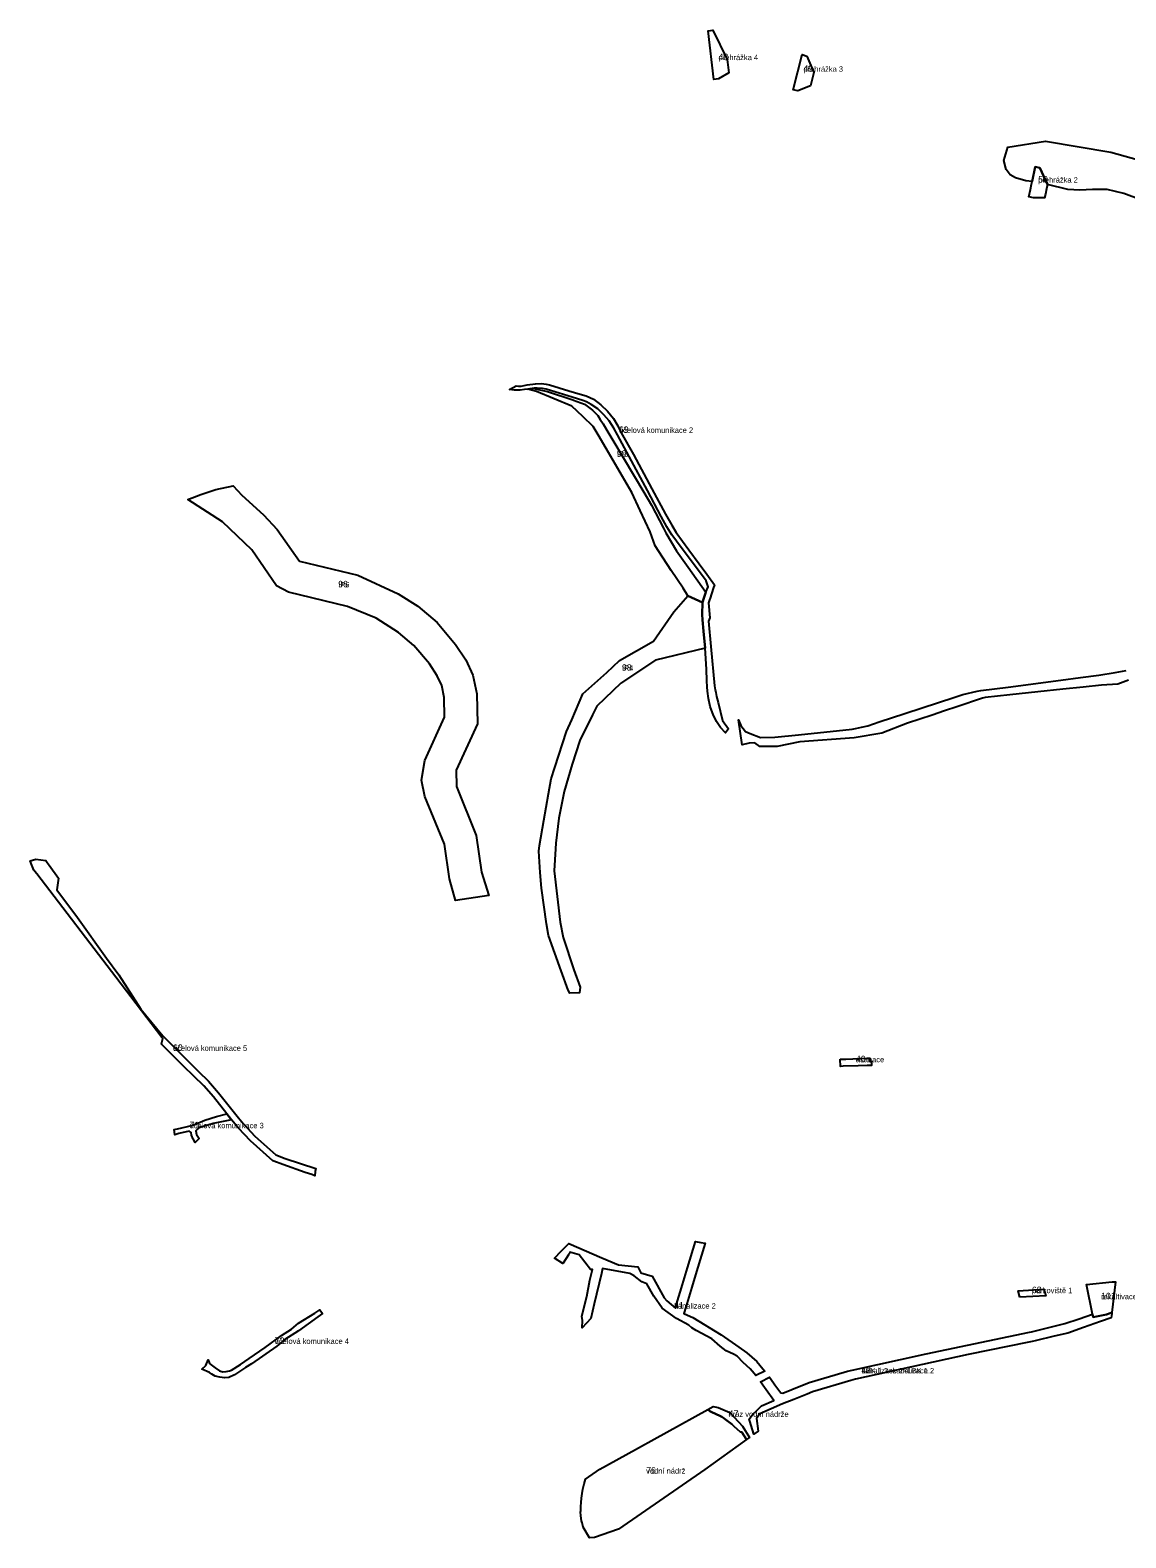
# Model space of a CAD drawing. Extents: x -535270 to -532834, y -1165802 to -1163869.
# Drawn here: x -535270 to -534261, y -1165554 to -1164165 of the extents above; entities that cross this region are included whole.
import ezdxf

# ---------------------------------------------------------------- set-up
doc = ezdxf.new("R2010")
doc.units = 0
for name, color, linetype in [('96070023', 7, 'Continuous'), ('96120023', 7, 'Continuous'), ('96140023', 7, 'Continuous'), ('ID_A', 7, 'Continuous'), ('ID_VPO', 7, 'Continuous'), ('ID_VPS', 7, 'Continuous')]:
    doc.layers.add(name, color=color, linetype=linetype)

msp = doc.modelspace()

# ---------------------------------------------------------------- linework, layer by layer
at = {"layer": '96070023'}
for points in [[(-534524.4, -1165113.2), (-534522, -1165113.1), (-534519, -1165113), (-534499.6, -1165112.1), (-534497, -1165112), (-534496.9, -1165115.3), (-534495.4, -1165115.2), (-534495.3, -1165118.9), (-534499.4, -1165119), (-534507.6, -1165119.3), (-534521.5, -1165119.6), (-534524, -1165119.7)], [(-534273.9, -1165318.2), (-534270.6, -1165318.2), (-534274, -1165346.4), (-534275.6, -1165346.9), (-534279.1, -1165348.2), (-534291.4, -1165350.8), (-534292, -1165347.8), (-534297.5, -1165320.7)]]:
    msp.add_lwpolyline(points, close=True, dxfattribs=at)
at = {"layer": '96120023'}
for points in [[(-534628.3, -1164192.3), (-534626.9, -1164204.7), (-534636.3, -1164210.1), (-534640.7, -1164210.6), (-534645.8, -1164165.9), (-534641.5, -1164165.3)], [(-534555.1, -1164189.1), (-534548.6, -1164204.4), (-534551.7, -1164216.5), (-534563.2, -1164221.3), (-534567.5, -1164220.3), (-534559.2, -1164187.6)], [(-534349.1, -1164312.1), (-534348, -1164307), (-534347.5, -1164304.6), (-534344.6, -1164291.1), (-534340.3, -1164292), (-534333.4, -1164307.5), (-534334.2, -1164311.5), (-534335.3, -1164316.4), (-534336, -1164319.7), (-534346.2, -1164319.7), (-534350.5, -1164318.8)], [(-534644.6, -1164690), (-534645.4, -1164692.8), (-534644.3, -1164706.7), (-534645.6, -1164709.7), (-534643.5, -1164733.1), (-534640.1, -1164769.3), (-534639.4, -1164772.9), (-534639.2, -1164773.8), (-534638.9, -1164775.4), (-534638.1, -1164779.1), (-534636.5, -1164784.7), (-534632.7, -1164801.2), (-534627.2, -1164808.9), (-534629.9, -1164812.5), (-534634.4, -1164807.5), (-534638.1, -1164802), (-534641.2, -1164795.7), (-534642.9, -1164791.6), (-534644, -1164788.3), (-534645.4, -1164781), (-534646.5, -1164774.2), (-534646.9, -1164770.1), (-534647, -1164764.5), (-534647.3, -1164753.7), (-534648.6, -1164734.4), (-534650.2, -1164718.7), (-534651.1, -1164708.5), (-534651.3, -1164703.4), (-534651, -1164692.3), (-534649.9, -1164688.6), (-534647.9, -1164682.8), (-534645.8, -1164678), (-534647.6, -1164672.4), (-534658.3, -1164658.1), (-534670.7, -1164641.7), (-534679.2, -1164630.1), (-534683.8, -1164622.8), (-534689, -1164613.3), (-534701.7, -1164589.4), (-534718.5, -1164558), (-534729.3, -1164538), (-534732.8, -1164531.8), (-534737.1, -1164525.2), (-534741.8, -1164519.5), (-534747.5, -1164514.1), (-534753.5, -1164510.1), (-534758, -1164507.7), (-534761.2, -1164506.4), (-534771.2, -1164503.3), (-534795, -1164495.9), (-534798.4, -1164495.2), (-534803.3, -1164494.9), (-534806.1, -1164495), (-534811.9, -1164495.8), (-534815.1, -1164496.4), (-534819, -1164496.8), (-534821.8, -1164496.9), (-534824.6, -1164496.8), (-534828.8, -1164496.4), (-534822.7, -1164493), (-534820.5, -1164493.1), (-534817.9, -1164493.1), (-534812.4, -1164492), (-534804.7, -1164491), (-534799.2, -1164490.8), (-534797.2, -1164490.9), (-534795, -1164491.2), (-534791.9, -1164491.9), (-534774, -1164497.4), (-534763.8, -1164500.7), (-534758.1, -1164502.1), (-534751.3, -1164505.2), (-534744.6, -1164510.4), (-534738.5, -1164516.3), (-534733.1, -1164523.1), (-534729.1, -1164529.8), (-534725.8, -1164536.1), (-534714.7, -1164556.1), (-534697.6, -1164587.6), (-534685, -1164611.1), (-534679.4, -1164621.2), (-534675.4, -1164627.9), (-534663.7, -1164644), (-534654.2, -1164656.8), (-534647.1, -1164666.5), (-534639.9, -1164676.1), (-534641.3, -1164679.6), (-534644, -1164688.3)], [(-535148.1, -1165091.7), (-535115.2, -1165124.5), (-535105.9, -1165133.4), (-535096.8, -1165144), (-535078.4, -1165167), (-535073.7, -1165172.7), (-535063.2, -1165184.1), (-535055.1, -1165191.2), (-535043.9, -1165201.1), (-535035.4, -1165204.6), (-535007.2, -1165213.8), (-535007.6, -1165216.5), (-535008.2, -1165220.6), (-535010.9, -1165219.4), (-535017.1, -1165217.3), (-535037.6, -1165210.2), (-535045.9, -1165206.9), (-535046.6, -1165206.7), (-535067.4, -1165188.4), (-535078.2, -1165176.7), (-535084.7, -1165168.8), (-535089, -1165163.4), (-535101.4, -1165147.9), (-535110.2, -1165137.6), (-535119.4, -1165128.8), (-535128.9, -1165119.5), (-535141.3, -1165107.1), (-535144, -1165104.4), (-535149.3, -1165099.3), (-535149, -1165097.8), (-535148, -1165094), (-535149, -1165093), (-535191.4, -1165037.5), (-535264.1, -1164942.3), (-535264.3, -1164942.1), (-535266.7, -1164938.9), (-535268.8, -1164934.5), (-535270.2, -1164930.3), (-535264.9, -1164928.9), (-535255.8, -1164930.2), (-535254.7, -1164931.8), (-535252.7, -1164934.5), (-535244.1, -1164946.4), (-535245.6, -1164957.1), (-535226.5, -1164982.7), (-535199.9, -1165019.9), (-535188.7, -1165035.4), (-535168.4, -1165067)], [(-535113.6, -1165171), (-535109.5, -1165169.3), (-535098.7, -1165165.8), (-535089, -1165163.4), (-535084.7, -1165168.8), (-535101.6, -1165172.4), (-535114.6, -1165176.2), (-535117.5, -1165179.1), (-535117.1, -1165182.5), (-535114.7, -1165186.1), (-535118.3, -1165189.9), (-535119.5, -1165187.7), (-535120, -1165186.8), (-535121.5, -1165183.2), (-535122, -1165180.7), (-535123.8, -1165179.5), (-535133.4, -1165181.6), (-535136.9, -1165182.6), (-535137.7, -1165177.7), (-535136, -1165177.4), (-535131.9, -1165176.7), (-535124.1, -1165174.8), (-535120.4, -1165173.7), (-535119.2, -1165173.2), (-535118.7, -1165173.1)], [(-534619, -1165386.7), (-534622.6, -1165384.9), (-534629.2, -1165381.7), (-534634.9, -1165377.4), (-534642.5, -1165370.8), (-534656.8, -1165362.9), (-534660.9, -1165360.4), (-534663.7, -1165358), (-534675, -1165352), (-534688.2, -1165342.4), (-534695.9, -1165331.3), (-534702.2, -1165320.1), (-534706.9, -1165318.1), (-534714, -1165312.5), (-534718.1, -1165310.4), (-534743.1, -1165306), (-534744.1, -1165310.6), (-534750.7, -1165338.5), (-534753.9, -1165352), (-534761.8, -1165360.4), (-534761.6, -1165353.7), (-534762.3, -1165349.7), (-534757.7, -1165331.8), (-534754.7, -1165316.6), (-534752.5, -1165306.9), (-534754.2, -1165306.7), (-534764.5, -1165293.4), (-534773.2, -1165290.9), (-534773.5, -1165292.1), (-534774.3, -1165293.3), (-534779.5, -1165300.9), (-534779.8, -1165301.4), (-534787.4, -1165296.3), (-534781.2, -1165289.9), (-534780.2, -1165288.9), (-534774.2, -1165282.7), (-534743.6, -1165295.9), (-534728.3, -1165302.6), (-534710.5, -1165304.2), (-534707.8, -1165310), (-534697.3, -1165312.9), (-534686.2, -1165332.9), (-534683.8, -1165335.5), (-534676, -1165342.3), (-534674.9, -1165338.6), (-534669.5, -1165320.6), (-534664.9, -1165305.3), (-534657.6, -1165281.1), (-534652.5, -1165281.9), (-534648.7, -1165282.5), (-534656.5, -1165308.5), (-534660.8, -1165323.1), (-534666.4, -1165341.5), (-534668.1, -1165347.2), (-534662.1, -1165350.1), (-534659.9, -1165351.1), (-534634, -1165367.1), (-534617.7, -1165378.2), (-534610.2, -1165383.4), (-534601, -1165391.4), (-534598.2, -1165394.8), (-534597, -1165396.3), (-534593.7, -1165400.3), (-534601.4, -1165404.2), (-534602, -1165404.5), (-534605.2, -1165400.5), (-534607, -1165398.3), (-534613.5, -1165392.3)], [(-534358.8, -1165332.2), (-534360.4, -1165326.3), (-534336.7, -1165324.9), (-534335, -1165330.9)], [(-535053.9, -1165378.5), (-535038.6, -1165367.5), (-535029.6, -1165361.8), (-535023.1, -1165356.1), (-535008.2, -1165346.9), (-535003.4, -1165344), (-535000.9, -1165347.4), (-535005.4, -1165350.5), (-535023, -1165363.3), (-535035.6, -1165371.2), (-535043, -1165377.3), (-535066.5, -1165393.6), (-535071.8, -1165397.2), (-535073.6, -1165398.4), (-535082, -1165403.9), (-535087.1, -1165406.3), (-535091.3, -1165406.7), (-535095.4, -1165406), (-535099.8, -1165404.9), (-535102.9, -1165403.1), (-535105, -1165401.8), (-535112, -1165398.6), (-535108.4, -1165395.2), (-535106.4, -1165390.1), (-535105, -1165393.3), (-535103.4, -1165394.6), (-535099.9, -1165397.3), (-535095.7, -1165400.1), (-535092.8, -1165401), (-535089.8, -1165400.6), (-535086.7, -1165400.2), (-535084.9, -1165399.6), (-535076.5, -1165394.3), (-535068.4, -1165388.8)], [(-534567, -1165426.4), (-534577.5, -1165430.6), (-534598.3, -1165439.8), (-534601.4, -1165444.1), (-534599.9, -1165455.7), (-534603.9, -1165458.5), (-534607.5, -1165446.4), (-534608.1, -1165444.5), (-534604.6, -1165440.1), (-534601.6, -1165437.2), (-534599.5, -1165435.2), (-534596.6, -1165432.4), (-534585.5, -1165427.4), (-534592.4, -1165417.5), (-534593.9, -1165415.5), (-534597.6, -1165410.3), (-534589.3, -1165406), (-534585.7, -1165411.1), (-534584.3, -1165413), (-534578.8, -1165420.5), (-534577.1, -1165420.7), (-534568.8, -1165417.4), (-534552.7, -1165411), (-534520.7, -1165401.4), (-534517.6, -1165400.5), (-534513.2, -1165399.4), (-534445, -1165384.4), (-534350, -1165364.5), (-534348.2, -1165364.1), (-534317.3, -1165356.6), (-534304.2, -1165352.1), (-534292, -1165347.8), (-534291.4, -1165350.8), (-534279.1, -1165348.2), (-534275.6, -1165346.9), (-534274, -1165346.4), (-534274.2, -1165347.7), (-534274.6, -1165351.3), (-534284.5, -1165354.7), (-534300.2, -1165360.2), (-534314.7, -1165365.3), (-534327.1, -1165368.3), (-534344.7, -1165372.5), (-534347.6, -1165373.2), (-534350.4, -1165373.8), (-534406.4, -1165385.1), (-534510, -1165407.9), (-534512.2, -1165408.4), (-534514.4, -1165408.9), (-534549.7, -1165419.5), (-534554.7, -1165421.5)], [(-534644.3, -1165437.2), (-534642.6, -1165438.1), (-534635.1, -1165441.6), (-534633.1, -1165442.5), (-534631.5, -1165443.8), (-534629.9, -1165445), (-534624.1, -1165449.2), (-534621.8, -1165451.3), (-534616.5, -1165456.3), (-534614.9, -1165456.7), (-534610.5, -1165463.3), (-534648.9, -1165491.1), (-534728.5, -1165546), (-534750.4, -1165553.6), (-534755.2, -1165554), (-534760.8, -1165544.1), (-534761.2, -1165542.7), (-534761.9, -1165540.2), (-534762.4, -1165538.3), (-534762.8, -1165536.1), (-534763.1, -1165533.5), (-534763.3, -1165530.3), (-534763.2, -1165528.9), (-534763.1, -1165525), (-534762.8, -1165521.5), (-534762.4, -1165517.4), (-534761.8, -1165513.2), (-534761.1, -1165509.1), (-534760, -1165504.3), (-534758.7, -1165499.8), (-534745.6, -1165490.7), (-534721.7, -1165477.5), (-534646.2, -1165435.7)], [(-534629.9, -1165445), (-534631.5, -1165443.8), (-534633.1, -1165442.5), (-534635.1, -1165441.6), (-534642.6, -1165438.1), (-534644.3, -1165437.2), (-534646.2, -1165435.7), (-534641.3, -1165433), (-534636.7, -1165433.9), (-534625.8, -1165438.4), (-534614.1, -1165451.1), (-534607.9, -1165461.4), (-534610.5, -1165463.3), (-534614.9, -1165456.7), (-534616.5, -1165456.3), (-534621.8, -1165451.3), (-534624.1, -1165449.2)]]:
    msp.add_lwpolyline(points, close=True, dxfattribs=at)
msp.add_lwpolyline([(-534258.6, -1164764.1), (-534268.5, -1164767.7), (-534283.7, -1164768.5), (-534300.5, -1164770.3), (-534319.1, -1164772.3), (-534342.1, -1164774.8), (-534367.9, -1164777.5), (-534390.8, -1164780), (-534393.1, -1164780.7), (-534416.8, -1164788.6), (-534428.1, -1164792.3), (-534439.6, -1164796.1), (-534462.2, -1164803.6), (-534485.8, -1164812.9), (-534511.4, -1164817.2), (-534561.3, -1164820.7), (-534582.3, -1164825.1), (-534598.1, -1164825.1), (-534603, -1164821.7), (-534608.1, -1164822.1), (-534614.6, -1164823.5), (-534618, -1164800.6), (-534615.6, -1164805.6), (-534611.4, -1164811.2), (-534607.2, -1164813), (-534597.6, -1164816.7), (-534584.4, -1164816.4), (-534562.7, -1164814.4), (-534513.1, -1164809), (-534510.1, -1164808.5), (-534504.6, -1164807.4), (-534498.8, -1164805.9), (-534488.5, -1164802.5), (-534464.6, -1164794.6), (-534418.7, -1164779.5), (-534411.4, -1164777.1), (-534398.2, -1164774), (-534394.8, -1164773.5), (-534369.6, -1164770.3), (-534321.1, -1164764), (-534302.8, -1164761.6), (-534286.1, -1164759.4), (-534271, -1164756.8), (-534260.9, -1164755)], dxfattribs=at)
at = {"layer": '96140023'}
msp.add_lwpolyline([(-534234.1, -1164326.6), (-534262.9, -1164315.8), (-534278.3, -1164312), (-534292, -1164312), (-534303.6, -1164312.7), (-534314.7, -1164312.2), (-534333.4, -1164307.5), (-534340.3, -1164292), (-534344.6, -1164291.1), (-534347.5, -1164304.6), (-534353.4, -1164304.2), (-534362.7, -1164301.4), (-534367.7, -1164298.6), (-534371.3, -1164293.5), (-534373.5, -1164285.2), (-534369.8, -1164273.2), (-534335.1, -1164267.4), (-534275, -1164277.7), (-534197.9, -1164299.2)], dxfattribs=at)
for points in [[(-534806.1, -1164495), (-534805.1, -1164495.5), (-534793.9, -1164498.2), (-534770.4, -1164505.9), (-534769.8, -1164506.1), (-534759.6, -1164509.9), (-534752.2, -1164515.4), (-534747.3, -1164520.3), (-534745.2, -1164523.8), (-534742.6, -1164528), (-534739, -1164533.8), (-534734.5, -1164541.3), (-534723.1, -1164560.4), (-534705, -1164590.8), (-534697.9, -1164602.7), (-534687, -1164624), (-534684.8, -1164628.2), (-534675.1, -1164644.9), (-534664.3, -1164659.9), (-534647.9, -1164682.8), (-534649.9, -1164688.6), (-534651, -1164692.3), (-534664.5, -1164686.4), (-534668.8, -1164679.2), (-534679.8, -1164663), (-534691.2, -1164645.5), (-534694.6, -1164640.2), (-534699.3, -1164627.5), (-534708.4, -1164607.7), (-534716.2, -1164591.1), (-534739.7, -1164550.6), (-534747, -1164538.1), (-534751.7, -1164530.2), (-534761.3, -1164521), (-534771.3, -1164511.5), (-534803.9, -1164498), (-534811.9, -1164495.8)], [(-534884.1, -1164947), (-534888.7, -1164915), (-534906.6, -1164871), (-534909.9, -1164856), (-534906.6, -1164838), (-534888.5, -1164798), (-534888.8, -1164780), (-534891.1, -1164769), (-534895.3, -1164760), (-534902.6, -1164749), (-534916.9, -1164732), (-534930.9, -1164720), (-534951.6, -1164707), (-534977.9, -1164696), (-535032.3, -1164683), (-535043.4, -1164677), (-535066.1, -1164644), (-535093, -1164618), (-535125.1, -1164597.6), (-535113.1, -1164592.9), (-535099.2, -1164588.5), (-535083.4, -1164584.9), (-535075.4, -1164593.5), (-535055.2, -1164611.6), (-535042.6, -1164625.2), (-535022.1, -1164654.4), (-534968.5, -1164667.4), (-534931.3, -1164684.5), (-534913.1, -1164695.8), (-534895.5, -1164710.8), (-534878.6, -1164731), (-534869.1, -1164745.3), (-534862.5, -1164759.5), (-534858.9, -1164776.6), (-534858.4, -1164804.2), (-534877.8, -1164847), (-534877.6, -1164861.9), (-534859.5, -1164907.1), (-534854.7, -1164940.7), (-534847.9, -1164962.3), (-534878.4, -1164967)], [(-534651.3, -1164703.4), (-534651.1, -1164708.5), (-534650.2, -1164718.7), (-534648.6, -1164734.4), (-534694.4, -1164745.5), (-534726.2, -1164766.6), (-534748.3, -1164788), (-534752.2, -1164795.8), (-534764, -1164819.5), (-534771, -1164841.5), (-534778.3, -1164866.5), (-534783.3, -1164891.2), (-534786.1, -1164914), (-534786.5, -1164919.3), (-534787.5, -1164939.6), (-534782.1, -1164986.9), (-534779.5, -1165001.1), (-534769.4, -1165030.7), (-534763.7, -1165046.7), (-534764.2, -1165052), (-534773.1, -1165052.2), (-534774.9, -1165049.6), (-534781.3, -1165031.6), (-534793, -1164999.3), (-534794.6, -1164988.3), (-534799.4, -1164955.5), (-534800.4, -1164941.1), (-534801.7, -1164921.5), (-534801.2, -1164916.2), (-534797.2, -1164893.3), (-534792.9, -1164868.8), (-534790.5, -1164854.9), (-534787.1, -1164844.3), (-534776.4, -1164811.4), (-534771.5, -1164800.4), (-534761.1, -1164776.5), (-534739.3, -1164756.8), (-534727.4, -1164746), (-534696.1, -1164728), (-534677.5, -1164700.9), (-534664.5, -1164686.4), (-534651, -1164692.3)], [(-534567, -1165426.4), (-534577.5, -1165430.6), (-534598.3, -1165439.8), (-534601.4, -1165444.1), (-534599.9, -1165455.7), (-534603.9, -1165458.5), (-534607.5, -1165446.4), (-534608.1, -1165444.5), (-534604.6, -1165440.1), (-534601.6, -1165437.2), (-534599.5, -1165435.2), (-534596.6, -1165432.4), (-534585.5, -1165427.4), (-534592.4, -1165417.5), (-534593.9, -1165415.5), (-534597.6, -1165410.3), (-534589.3, -1165406), (-534585.7, -1165411.1), (-534584.3, -1165413), (-534578.8, -1165420.5), (-534577.1, -1165420.7), (-534568.8, -1165417.4), (-534552.7, -1165411), (-534520.7, -1165401.4), (-534517.6, -1165400.5), (-534513.2, -1165399.4), (-534445, -1165384.4), (-534350, -1165364.5), (-534348.2, -1165364.1), (-534317.3, -1165356.6), (-534304.2, -1165352.1), (-534292, -1165347.8), (-534291.4, -1165350.8), (-534279.1, -1165348.2), (-534275.6, -1165346.9), (-534274, -1165346.4), (-534274.2, -1165347.7), (-534274.6, -1165351.3), (-534284.5, -1165354.7), (-534300.2, -1165360.2), (-534314.7, -1165365.3), (-534327.1, -1165368.3), (-534344.7, -1165372.5), (-534347.6, -1165373.2), (-534350.4, -1165373.8), (-534406.4, -1165385.1), (-534510, -1165407.9), (-534512.2, -1165408.4), (-534514.4, -1165408.9), (-534549.7, -1165419.5), (-534554.7, -1165421.5)]]:
    msp.add_lwpolyline(points, close=True, dxfattribs=at)

# ---------------------------------------------------------------- texts
at = {"layer": '96070023'}
for s, p in [('asanace', (-534509.8, -1165115.9)), ('rekultivace skládky', (-534284, -1165334.2))]:
    msp.add_text(s, height=5, rotation=360, dxfattribs=at).set_placement(p)
at = {"layer": '96120023'}
for s, rotation, p in [('přehrážka 4', 360, (-534636.3, -1164192.9)), ('přehrážka 3', 0, (-534558.1, -1164203.6)), ('přehrážka 2', 0, (-534341.9, -1164305.7)), ('účelová komunikace 2', 0, (-534728, -1164536.2)), ('účelová komunikace 5', 360, (-535138.7, -1165105.4)), ('účelová komunikace 3', 0, (-535123.4, -1165176.7)), ('parkoviště 1', 360, (-534347.7, -1165328.6)), ('kanalizace 2', 360, (-534677.2, -1165342.8)), ('účelová komunikace 4', 360, (-535045, -1165375.3)), ('kanalizace 2×LBK 1.2', 360, (-534504.7, -1165402.5)), ('hráz vodní nádrže', 0, (-534627, -1165442.5)), ('vodní nádrž', 0, (-534702.9, -1165494.8))]:
    msp.add_text(s, height=5, rotation=rotation, dxfattribs=at).set_placement(p)
at = {"layer": '96140023'}
for s, rotation, p in [('IP3', 0, (-534729.9, -1164558.3)), ('IP6', 360, (-534986.5, -1164678.5)), ('IP4', 360, (-534725.2, -1164755.3)), ('LBK 1.2×kanalizace 2', 360, (-534504.7, -1165402.5))]:
    msp.add_text(s, height=5, rotation=rotation, dxfattribs=at).set_placement(p)
at = {"layer": 'ID_A'}
for s, p in [('40', (-534509.8, -1165115.9)), ('101', (-534284, -1165334.2))]:
    msp.add_text(s, height=6, rotation=360, dxfattribs=at).set_placement(p)
at = {"layer": 'ID_VPO'}
for s, rotation, p in [('99', 0, (-534729.9, -1164558.3)), ('96', 0, (-534986.5, -1164678.5)), ('98', 360, (-534725.2, -1164755.3))]:
    msp.add_text(s, height=6, rotation=rotation, dxfattribs=at).set_placement(p)
msp.add_text('42', height=6, dxfattribs=at).set_placement((-534504.7, -1165402.5))
at = {"layer": 'ID_VPS'}
for s, rotation, p in [('48', 360, (-534636.3, -1164192.9)), ('49', 0, (-534558.1, -1164203.6)), ('50', 0, (-534341.9, -1164305.7)), ('69', 360, (-534728, -1164536.2)), ('60', 0, (-535138.7, -1165105.4)), ('71', 0, (-535123.4, -1165176.7)), ('68', 360, (-534347.7, -1165328.6)), ('72', 360, (-535045, -1165375.3)), ('47', 0, (-534627, -1165442.5)), ('76', 360, (-534702.9, -1165494.8))]:
    msp.add_text(s, height=6, rotation=rotation, dxfattribs=at).set_placement(p)
for s, p in [('41', (-534677.2, -1165342.8)), ('42', (-534504.7, -1165402.5))]:
    msp.add_text(s, height=6, dxfattribs=at).set_placement(p)

doc.saveas('drawing.dxf')
